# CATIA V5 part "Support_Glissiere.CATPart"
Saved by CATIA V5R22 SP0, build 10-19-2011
Part number: Support_Glissiere
Bounding box of the stored display mesh (mm): x -25 to 25, y -25 to 25, z 0 to 6
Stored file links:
  U:\S9A\PER\CAO\Assemblage\Cadre\Chariot_X\Support_Glissiere.CATPart
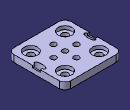
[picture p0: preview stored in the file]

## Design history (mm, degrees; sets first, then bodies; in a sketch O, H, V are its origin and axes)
Body1 (main body)
  Sketch1 on xy-plane, origin (0, 0, 0), H (1, 0, 0), V (0, 1, 0)
    line L1 (25, 25) -> (25, -25)
    line L2 (25, -25) -> (-25, -25)
    line L3 (-25, -25) -> (-25, 25)
    line L4 (-25, 25) -> (25, 25)
    length L1 = 50
    length L4 = 50
    vertical: L1 V, L3 V
    horizontal: L2 H, L4 H
    equidistance: L1 L3 O, L2 L4 O
  Pad1: profile Sketch1, direction (0, 0, 1), length 6
  Sketch2 on end face of Pad1, origin (-18.0423, 18.0423, 6), H (1, 0, 0), V (0, 1, 0)
    point P1 (3.0423, -3.0423)
    reference projected line E1 (43.0423, 6.9577) -> (-6.9577, 6.9577) from edge [face of Pad1 from Sketch1.L4 | end face of Pad1]
    reference projected line E2 (-6.9577, 6.9577) -> (-6.9577, -43.0423) from edge [face of Pad1 from Sketch1.L3 | end face of Pad1]
    distance P1 E1 = 10
    distance P1 E2 = 10
  Hole1: placed by Sketch2, at (-15, 15, 6) direction (0, 0, -1), diameter 6, depth 6, counterbore diameter 12, counterbore depth 3
  RectPattern1: of Hole1, direction 1 instances 2, spacing 30, along end face of Pad1, direction 2 instances 2, spacing 30, along end face of Pad1 reversed
  Sketch3 on end face of Pad1, origin (9.3229, -1.3333, 6), H (1, 0, 0), V (0, 1, 0)
    point P1 (-9.3229, 1.3333)
    reference projected line E1 (-34.3229, 26.3333) -> (-34.3229, -23.6667) from edge [face of Pad1 from Sketch1.L3 | end face of Pad1]
    reference projected line E2 (15.6771, 26.3333) -> (-34.3229, 26.3333) from edge [face of Pad1 from Sketch1.L4 | end face of Pad1]
    distance P1 E1 = 25
    distance P1 E2 = 25
  Hole2: placed by Sketch3, at (0, 0, 6) direction (0, 0, -1), diameter 5, depth 6, threaded, thread diameter 6.6, thread depth 6, pitch 1
  RectPattern2: of Hole2, direction 1 instances 3, spacing 10, along end face of Pad1, Nu 2
  RectPattern3: of Hole2, direction 1 instances 1, spacing 10, along end face of Pad1, direction 2 instances 3, spacing 10, along end face of Pad1, Nv 2
  Fillet1: radius 5, on edge [face of Pad1 from Sketch1.L1 | face of Pad1 from Sketch1.L2]; edge [face of Pad1 from Sketch1.L4 | face of Pad1 from Sketch1.L1]; edge [face of Pad1 from Sketch1.L3 | face of Pad1 from Sketch1.L4]; edge [face of Pad1 from Sketch1.L2 | face of Pad1 from Sketch1.L3]
  Sketch4 on end face of Pad1, origin (0, 0, 6), H (1, 0, 0), V (0, 1, 0)
    line L1 (23, 3.5) -> (25, 3.5)
    line L2 (25, 3.5) -> (25, -3.5)
    line L3 (25, -3.5) -> (23, -3.5)
    line L4 (23, -3.5) -> (23, 3.5)
    reference projected line E1 (25, -25) -> (25, 25) from edge [face of Pad1 from Sketch1.L1 | end face of Pad1]
    length L2 = 7
    length L3 = 2
    distance L3 H = 3.5
    horizontal: L1 H, L3 H
    vertical: L2 V, L4 V
    coincidence: L2 E1
  Pocket1: profile Sketch4, direction (0, 0, -1), length 2
  RectPattern4: of Pocket1, direction 1 instances 2, spacing 48, along end face of Pad1 reversed
  Sketch5 on end face of Pad1, origin (0, 0, 6), H (1, 0, 0), V (0, 1, 0)
    point P1 (22, 0)
    ellipse A1 centre (22, 0) semi-axes 5, 2 rotation 270
    "Radius" A1 = 5
    distance P1 A1 = 2
    distance P1 O = 22
    coincidence: P1 H
  Pocket2: profile Sketch5, direction (0, 0, -1), length 6
  RectPattern5: of Pocket2, direction 1 instances 2, spacing 44, along end face of Pad1 reversed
